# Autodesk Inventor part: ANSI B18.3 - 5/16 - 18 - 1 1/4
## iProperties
Comments: To add or edit properties for Autodesk Inventor files, use iProperties.
Created: 2005-06
Part Number: ANSI B18.3 - 5/16 - 18 - 1 1/4
Vendor: Autodesk Inc.
Document SubType Name: Modeling
Designer: John Blackburn
Material: Default
Description: Hexagon Socket Head Cap Screw
Standard: ANSI B18.3
Alert: To add or edit properties for Autodesk Inventor files, use iProperties.
Control State: 0
Master: False
Checked Out: False
Shininess: 64.0
Length Units: 11272
Angle Units: 11279
Time Units: 11290
Mass Units: 11286
Length Display Precision: 3
Angle Display Precision: 2
Compacted: True
EGR: 3
Classification: un/spsc 31161501
Density: 0.0
Volumn: 0.0
Area: 0.0
PropertySet Name: Model Information
Author: John Blackburn
Revision Number: 8
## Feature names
1. Body [Revolution]
2. Slot [Extrusion]
3. Fillet1
4. Chamfer1
